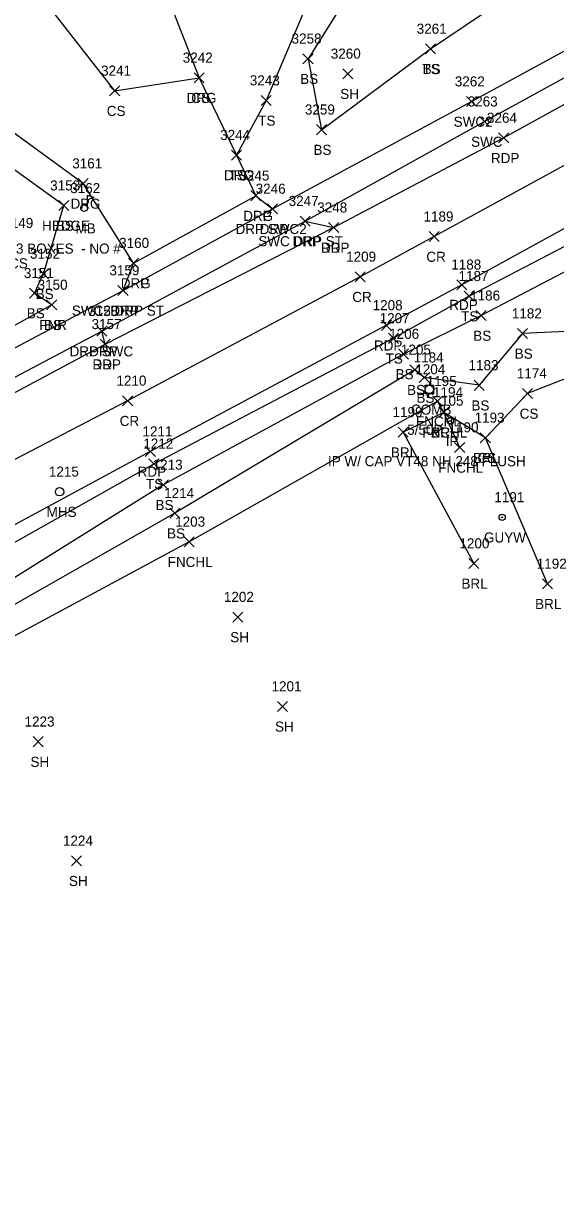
# Model space of a CAD drawing. Extents: x 1477930 to 1480780, y 774090 to 784647.
# Drawn here: x 1479576.9 to 1479682.6, y 774628 to 774857.9 of the extents above; entities that cross this region are included whole.
import ezdxf

# ---------------------------------------------------------------- set-up
doc = ezdxf.new("R2010")
doc.units = 0
for name, color, linetype in [('L_A', 7, 'Continuous'), ('L_C', 7, 'Continuous'), ('L_I', 7, 'Continuous'), ('L_TIC', 7, 'Continuous'), ('LABL', 7, 'Continuous'), ('LAHR', 7, 'Continuous'), ('LELB', 7, 'Continuous'), ('LFNC', 7, 'Continuous'), ('LMB', 7, 'Continuous'), ('M_A', 7, 'Continuous'), ('M_C', 7, 'Continuous'), ('M_I', 7, 'Continuous'), ('MPIR', 7, 'Continuous'), ('P_A', 7, 'Continuous'), ('P_I', 7, 'Continuous'), ('P_TIC', 7, 'Continuous'), ('PET', 7, 'Continuous'), ('PRC', 7, 'Continuous'), ('R_A', 7, 'Continuous'), ('R_I', 7, 'Continuous'), ('R_TIC', 7, 'Continuous'), ('RDG', 7, 'Continuous'), ('RDP', 7, 'Continuous'), ('RSW', 7, 'Continuous'), ('U_A', 7, 'Continuous'), ('U_C', 7, 'Continuous'), ('U_I', 7, 'Continuous'), ('UP', 7, 'Continuous'), ('UPGW', 7, 'Continuous'), ('USMH', 7, 'Continuous')]:
    doc.layers.add(name, color=color, linetype=linetype)

msp = doc.modelspace()

# ---------------------------------------------------------------- linework, layer by layer
at = {"layer": 'L_TIC'}
for points in [[(1479632.41, 774849.84), (1479634.41, 774851.84)], [(1479634.41, 774849.84), (1479632.41, 774851.84)], [(1479656.71, 774851.79), (1479658.71, 774853.79)], [(1479658.71, 774851.79), (1479656.71, 774853.79)], [(1479656.71, 774851.79), (1479658.71, 774853.79)], [(1479658.71, 774851.79), (1479656.71, 774853.79)], [(1479610.81, 774846.06), (1479612.81, 774848.06)], [(1479612.81, 774846.06), (1479610.81, 774848.06)], [(1479640.31, 774846.85), (1479642.31, 774848.85)], [(1479642.31, 774846.85), (1479640.31, 774848.85)], [(1479594.04, 774843.48), (1479596.04, 774845.48)], [(1479596.04, 774843.48), (1479594.04, 774845.48)], [(1479624.12, 774841.55), (1479626.12, 774843.55)], [(1479626.12, 774841.55), (1479624.12, 774843.55)], [(1479635.06, 774835.76), (1479637.06, 774837.76)], [(1479637.06, 774835.76), (1479635.06, 774837.76)], [(1479618.24, 774830.72), (1479620.24, 774832.72)], [(1479620.24, 774830.72), (1479618.24, 774832.72)], [(1479583.95, 774820.7), (1479585.95, 774822.7)], [(1479585.95, 774820.7), (1479583.95, 774822.7)], [(1479583.95, 774820.7), (1479585.95, 774822.7)], [(1479585.95, 774820.7), (1479583.95, 774822.7)], [(1479579.94, 774807.15), (1479581.94, 774809.15)], [(1479581.94, 774807.15), (1479579.94, 774809.15)], [(1479578.16, 774803.32), (1479580.16, 774805.32)], [(1479580.16, 774803.32), (1479578.16, 774805.32)], [(1479664.38, 774802.72), (1479666.38, 774804.72)], [(1479666.38, 774802.72), (1479664.38, 774804.72)], [(1479581.54, 774801), (1479583.54, 774803)], [(1479583.54, 774801), (1479581.54, 774803)], [(1479581.54, 774801), (1479583.54, 774803)], [(1479583.54, 774801), (1479581.54, 774803)], [(1479666.75, 774798.87), (1479668.75, 774800.87)], [(1479668.75, 774798.87), (1479666.75, 774800.87)], [(1479674.98, 774795.31), (1479676.98, 774797.31)], [(1479676.98, 774795.31), (1479674.98, 774797.31)], [(1479649.39, 774794.36), (1479651.39, 774796.36)], [(1479651.39, 774794.36), (1479649.39, 774796.36)], [(1479651.34, 774791.25), (1479653.34, 774793.25)], [(1479653.34, 774791.25), (1479651.34, 774793.25)], [(1479653.62, 774788.12), (1479655.62, 774790.12)], [(1479655.62, 774788.12), (1479653.62, 774790.12)], [(1479655.48, 774786.57), (1479657.48, 774788.57)], [(1479657.48, 774786.57), (1479655.48, 774788.57)], [(1479666.39, 774785.04), (1479668.39, 774787.04)], [(1479668.39, 774785.04), (1479666.39, 774787.04)], [(1479675.96, 774783.41), (1479677.96, 774785.41)], [(1479677.96, 774783.41), (1479675.96, 774785.41)], [(1479658.08, 774781.89), (1479660.08, 774783.89)], [(1479660.08, 774781.89), (1479658.08, 774783.89)], [(1479659.34, 774779.67), (1479661.34, 774781.67)], [(1479661.34, 774779.67), (1479659.34, 774781.67)], [(1479659.34, 774779.67), (1479661.34, 774781.67)], [(1479661.34, 774779.67), (1479659.34, 774781.67)], [(1479651.31, 774775.72), (1479653.31, 774777.72)], [(1479653.31, 774775.72), (1479651.31, 774777.72)], [(1479667.59, 774774.62), (1479669.59, 774776.62)], [(1479669.59, 774774.62), (1479667.59, 774776.62)], [(1479667.59, 774774.62), (1479669.59, 774776.62)], [(1479669.59, 774774.62), (1479667.59, 774776.62)], [(1479662.5, 774772.7), (1479664.5, 774774.7)], [(1479664.5, 774772.7), (1479662.5, 774774.7)], [(1479601.85, 774769.48), (1479603.85, 774771.48)], [(1479603.85, 774769.48), (1479601.85, 774771.48)], [(1479603.7, 774765.29), (1479605.7, 774767.29)], [(1479605.7, 774765.29), (1479603.7, 774767.29)], [(1479606, 774759.65), (1479608, 774761.65)], [(1479608, 774759.65), (1479606, 774761.65)], [(1479608.82, 774753.99), (1479610.82, 774755.99)], [(1479610.82, 774753.99), (1479608.82, 774755.99)], [(1479665.31, 774749.69), (1479667.31, 774751.69)], [(1479667.31, 774749.69), (1479665.31, 774751.69)], [(1479679.92, 774745.65), (1479681.92, 774747.65)], [(1479681.92, 774745.65), (1479679.92, 774747.65)], [(1479618.48, 774739.06), (1479620.48, 774741.06)], [(1479620.48, 774739.06), (1479618.48, 774741.06)], [(1479627.37, 774721.32), (1479629.37, 774723.32)], [(1479629.37, 774721.32), (1479627.37, 774723.32)], [(1479578.85, 774714.33), (1479580.85, 774716.33)], [(1479580.85, 774714.33), (1479578.85, 774716.33)], [(1479586.48, 774690.7), (1479588.48, 774692.7)], [(1479588.48, 774690.7), (1479586.48, 774692.7)]]:
    msp.add_lwpolyline(points, dxfattribs=at)
at = {"layer": 'LABL'}
msp.add_lwpolyline([(1479680.92, 774746.65), (1479668.59, 774775.62), (1479660.34, 774780.67), (1479652.31, 774776.72), (1479666.31, 774750.69)], dxfattribs=at)
at = {"layer": 'LAHR'}
msp.add_lwpolyline([(1479584.95, 774821.7), (1479570.44, 774832.18)], dxfattribs=at)
at = {"layer": 'LELB'}
for points in [[(1479657.71, 774852.79), (1479678.77, 774867.01), (1479701, 774889.08), (1479732.59, 774912.18), (1479741.3, 774922.23), (1479718.58, 774955.17), (1479686.39, 774981.9), (1479667.59, 775015.02), (1479668.33, 775036.3)], [(1479580.44, 774995.69), (1479587.48, 775002.68), (1479612.24, 774984.69), (1479628.11, 774970.45), (1479636.94, 774956.73), (1479624.94, 774926.71), (1479649.32, 774906.86), (1479653.38, 774932.32), (1479686.61, 774909.39), (1479687.43, 774900.61), (1479665.73, 774876.56), (1479654.12, 774867.16), (1479644.81, 774869.01), (1479633.41, 774850.84), (1479636.06, 774836.76), (1479657.71, 774852.79)], [(1479581.64, 774979.15), (1479580.44, 774995.69), (1479607.54, 774976.74), (1479621.25, 774963.52), (1479616.74, 774946.08), (1479607.55, 774933.66), (1479642.59, 774883.82), (1479625.12, 774842.55), (1479619.24, 774831.72)], [(1479515.09, 774886.51), (1479547.39, 774880.5), (1479577.54, 774866.92), (1479595.04, 774844.48), (1479611.81, 774847.06)], [(1479759.78, 774845.84), (1479743.76, 774848.1), (1479715.88, 774830.05), (1479665.38, 774803.72), (1479650.39, 774795.36), (1479602.85, 774770.48), (1479561.12, 774746.99), (1479522.68, 774719.79), (1479509.66, 774713.24), (1479482.17, 774702.33), (1479465.55, 774693.3), (1479450.04, 774680.68), (1479444.99, 774662.35), (1479439.28, 774645.05), (1479436.33, 774630.12), (1479434.69, 774607.73), (1479420.75, 774561.37), (1479408.24, 774515.83), (1479404.08, 774492.53), (1479401.08, 774483.2), (1479386.93, 774431.62)], [(1479759.78, 774845.84), (1479747.61, 774840.08), (1479717.72, 774826.7), (1479693.11, 774813.12), (1479667.75, 774799.87), (1479652.34, 774792.25), (1479604.7, 774766.29), (1479564.8, 774741.45), (1479523.94, 774717.4), (1479484.23, 774697.29), (1479467.35, 774689.75), (1479454.86, 774676.9), (1479444.99, 774662.35), (1479436.47, 774645.61)], [(1479755.47, 774826.43), (1479747.52, 774835), (1479732.81, 774826.8), (1479711.85, 774814.98), (1479703.35, 774801.53), (1479690.31, 774796.96), (1479675.98, 774796.31), (1479667.39, 774786.04), (1479656.48, 774787.57), (1479654.62, 774789.12), (1479607, 774760.65), (1479567.24, 774738.02), (1479525.29, 774711.93), (1479486.59, 774691.55), (1479469.23, 774685.68), (1479454.86, 774676.9)], [(1479767.9, 774827.58), (1479755.47, 774826.43), (1479737.02, 774821.5), (1479724.16, 774814.54), (1479699.51, 774793.2), (1479676.96, 774784.41), (1479668.59, 774775.62)], [(1479582.54, 774802), (1479579.16, 774804.32), (1479580.94, 774808.15), (1479584.95, 774821.7)]]:
    msp.add_lwpolyline(points, dxfattribs=at)
at = {"layer": 'LFNC'}
for points in [[(1479557.42, 774788.11), (1479582.54, 774802)], [(1479663.5, 774773.7), (1479660.34, 774780.67), (1479659.08, 774782.89), (1479609.82, 774754.99), (1479569.72, 774733.43), (1479526.46, 774709.45), (1479487.86, 774688.03), (1479452.66, 774667.9), (1479445.76, 774640.86), (1479438.34, 774612.12), (1479428.73, 774573.41), (1479420.36, 774539.52), (1479411.98, 774506.91), (1479408.88, 774492.5)]]:
    msp.add_lwpolyline(points, dxfattribs=at)
at = {"layer": 'LMB'}
for p, q in [((1479589.62, 774823.77), (1479590.92, 774823.39)), ((1479589.63, 774821.18), (1479589.63, 774823.77)), ((1479589.63, 774822.87), (1479590.91, 774823.38)), ((1479588.97, 774821.17), (1479588.97, 774821.17))]:
    msp.add_line(p, q, dxfattribs=at)
msp.add_circle((1479588.97, 774821.17), 0.656, dxfattribs=at)
at = {"layer": 'MPIR'}
for radius in [0.625, 0.0833]:
    msp.add_circle((1479661.67, 774778.99), radius, dxfattribs=at)
at = {"layer": 'P_TIC'}
for points in [[(1479671.22, 774834.12), (1479673.22, 774836.12)], [(1479673.22, 774834.12), (1479671.22, 774836.12)], [(1479637.49, 774816.33), (1479639.49, 774818.33)], [(1479639.49, 774816.33), (1479637.49, 774818.33)], [(1479657.45, 774814.54), (1479659.45, 774816.54)], [(1479659.45, 774814.54), (1479657.45, 774816.54)], [(1479642.75, 774806.57), (1479644.75, 774808.57)], [(1479644.75, 774806.57), (1479642.75, 774808.57)], [(1479662.95, 774805), (1479664.95, 774807)], [(1479664.95, 774805), (1479662.95, 774807)], [(1479648, 774796.94), (1479650, 774798.94)], [(1479650, 774796.94), (1479648, 774798.94)], [(1479592.15, 774793.19), (1479594.15, 774795.19)], [(1479594.15, 774793.19), (1479592.15, 774795.19)], [(1479596.62, 774781.97), (1479598.62, 774783.97)], [(1479598.62, 774781.97), (1479596.62, 774783.97)], [(1479601.12, 774771.9), (1479603.12, 774773.9)], [(1479603.12, 774771.9), (1479601.12, 774773.9)]]:
    msp.add_lwpolyline(points, dxfattribs=at)
at = {"layer": 'PET'}
for points in [[(1479458.85, 774725.87), (1479463.75, 774725.49), (1479503.78, 774746.04), (1479529.26, 774759.88), (1479547.26, 774769.69), (1479593.15, 774794.19), (1479638.49, 774817.33), (1479672.22, 774835.12), (1479713.57, 774857.96), (1479753.19, 774879.74), (1479794.61, 774902.46), (1479830.33, 774920.88), (1479861.74, 774937.83), (1479877.76, 774946.85), (1479905.13, 774960.92), (1479936.65, 774977.61), (1479958.81, 774989.4), (1479973, 774995.93), (1480008.35, 775014.95)], [(1479713.99, 774833.47), (1479663.95, 774806), (1479649, 774797.94), (1479602.12, 774772.9), (1479559.82, 774750.06), (1479518.06, 774728.17), (1479475.57, 774706.69), (1479465.7, 774701.25), (1479434.17, 774686.11), (1479428.66, 774666.26), (1479418.77, 774633.96), (1479413.82, 774614.69), (1479404.23, 774566.57), (1479393.7, 774517.71), (1479389.34, 774499.77)]]:
    msp.add_lwpolyline(points, dxfattribs=at)
at = {"layer": 'PRC'}
msp.add_lwpolyline([(1480015.89, 775005.87), (1479971.79, 774982.46), (1479929.14, 774959.03), (1479892.61, 774942.34), (1479860.44, 774925.31), (1479806.49, 774896.54), (1479658.45, 774815.54), (1479643.75, 774807.57), (1479597.62, 774782.97), (1479555.61, 774761.16), (1479513.42, 774740.32), (1479471, 774718.6), (1479432.73, 774701.1), (1479418.32, 774694.97), (1479344.83, 774660.92), (1479298.6, 774640.39), (1479262.12, 774624.4), (1479219.63, 774609.01), (1479186.74, 774593.83)], dxfattribs=at)
at = {"layer": 'R_TIC'}
for points in [[(1479610.81, 774846.06), (1479612.81, 774848.06)], [(1479612.81, 774846.06), (1479610.81, 774848.06)], [(1479664.84, 774841.34), (1479666.84, 774843.34)], [(1479666.84, 774841.34), (1479664.84, 774843.34)], [(1479667.4, 774837.36), (1479669.4, 774839.36)], [(1479669.4, 774837.36), (1479667.4, 774839.36)], [(1479618.24, 774830.72), (1479620.24, 774832.72)], [(1479620.24, 774830.72), (1479618.24, 774832.72)], [(1479587.8, 774825.08), (1479589.8, 774827.08)], [(1479589.8, 774825.08), (1479587.8, 774827.08)], [(1479622.05, 774822.66), (1479624.05, 774824.66)], [(1479624.05, 774822.66), (1479622.05, 774824.66)], [(1479622.05, 774822.66), (1479624.05, 774824.66)], [(1479624.05, 774822.66), (1479622.05, 774824.66)], [(1479625.34, 774820.05), (1479627.34, 774822.05)], [(1479627.34, 774820.05), (1479625.34, 774822.05)], [(1479625.34, 774820.05), (1479627.34, 774822.05)], [(1479627.34, 774820.05), (1479625.34, 774822.05)], [(1479631.83, 774817.63), (1479633.83, 774819.63)], [(1479633.83, 774817.63), (1479631.83, 774819.63)], [(1479631.83, 774817.63), (1479633.83, 774819.63)], [(1479633.83, 774817.63), (1479631.83, 774819.63)], [(1479637.49, 774816.33), (1479639.49, 774818.33)], [(1479639.49, 774816.33), (1479637.49, 774818.33)], [(1479597.76, 774809.29), (1479599.76, 774811.29)], [(1479599.76, 774809.29), (1479597.76, 774811.29)], [(1479597.76, 774809.29), (1479599.76, 774811.29)], [(1479599.76, 774809.29), (1479597.76, 774811.29)], [(1479595.7, 774803.86), (1479597.7, 774805.86)], [(1479597.7, 774803.86), (1479595.7, 774805.86)], [(1479595.7, 774803.86), (1479597.7, 774805.86)], [(1479597.7, 774803.86), (1479595.7, 774805.86)], [(1479591.5, 774795.78), (1479593.5, 774797.78)], [(1479593.5, 774795.78), (1479591.5, 774797.78)], [(1479591.5, 774795.78), (1479593.5, 774797.78)], [(1479593.5, 774795.78), (1479591.5, 774797.78)], [(1479592.15, 774793.19), (1479594.15, 774795.19)], [(1479594.15, 774793.19), (1479592.15, 774795.19)]]:
    msp.add_lwpolyline(points, dxfattribs=at)
at = {"layer": 'RDG'}
for points in [[(1479582.37, 774920.59), (1479606.56, 774913.22), (1479625.75, 774898.28), (1479624.88, 774886.81), (1479614.93, 774873.93), (1479610.96, 774876.63), (1479604.69, 774865.39), (1479611.81, 774847.06), (1479619.24, 774831.72), (1479623.05, 774823.66)], [(1479598.76, 774810.29), (1479588.8, 774826.08), (1479565.98, 774842.71), (1479549.85, 774844.2), (1479543.64, 774826.73), (1479535.87, 774827.58), (1479537.4, 774832.24), (1479514.07, 774836.92)]]:
    msp.add_lwpolyline(points, dxfattribs=at)
at = {"layer": 'RDP'}
for points in [[(1479596.7, 774804.86), (1479598.76, 774810.29), (1479623.05, 774823.66), (1479626.34, 774821.05)], [(1479632.83, 774818.63), (1479638.49, 774817.33)], [(1479593.15, 774794.19), (1479592.5, 774796.78)]]:
    msp.add_lwpolyline(points, dxfattribs=at)
at = {"layer": 'RSW'}
for points in [[(1479454.05, 774732.2), (1479457.36, 774735.51), (1479461.55, 774734.41), (1479499.97, 774753.7), (1479531.62, 774770.46), (1479545.78, 774777.94), (1479596.7, 774804.86), (1479626.34, 774821.05), (1479665.84, 774842.34), (1479709.72, 774866.29), (1479748.23, 774887.23), (1479790.98, 774910.55), (1479825.88, 774929.42), (1479857.89, 774946.35), (1479880.81, 774958.36), (1479898.02, 774967.81), (1479932.31, 774985.56), (1479966.42, 775003.67), (1480005.03, 775023.74)], [(1479458.85, 774725.87), (1479459.6, 774730), (1479502.04, 774749.23), (1479530.65, 774764.31), (1479546.64, 774772.58), (1479592.5, 774796.78), (1479632.83, 774818.63), (1479668.4, 774838.36), (1479711.89, 774862.21), (1479750.54, 774883.44), (1479792.95, 774906.12), (1479828.15, 774924.96), (1479859.81, 774941.82), (1479882.29, 774953.43), (1479899.45, 774962.93), (1479935.39, 774981.77), (1479958.84, 774993.68), (1479967.68, 774998.52), (1480006.53, 775018.83)]]:
    msp.add_lwpolyline(points, dxfattribs=at)
at = {"layer": 'UP'}
for p, q in [((1479656.63, 774784.38), (1479656.63, 774786.05)), ((1479656.63, 774786.05), (1479658.29, 774786.05)), ((1479657.71, 774786.88), (1479657.46, 774786.05)), ((1479657.46, 774785.22), (1479657.46, 774785.22)), ((1479658.29, 774786.05), (1479658.29, 774784.38)), ((1479658.29, 774784.38), (1479656.63, 774784.38)), ((1479657.21, 774783.55), (1479657.46, 774784.38))]:
    msp.add_line(p, q, dxfattribs=at)
msp.add_circle((1479657.46, 774785.22), 0.833, dxfattribs=at)
at = {"layer": 'UPGW'}
for radius in [0.625, 0.0833]:
    msp.add_circle((1479671.93, 774759.85), radius, dxfattribs=at)
at = {"layer": 'USMH'}
for p, q in [((1479584.12, 774764.92), (1479584.12, 774764.92)), ((1479584.95, 774764.92), (1479584.95, 774764.92))]:
    msp.add_line(p, q, dxfattribs=at)
msp.add_circle((1479584.12, 774764.92), 0.833, dxfattribs=at)

# ---------------------------------------------------------------- texts
at = {"layer": 'L_A'}
for s, p in [('TS', (1479656.12, 774847.79)), ('BS', (1479656.15, 774847.79)), ('BS', (1479631.85, 774845.84)), ('SH', (1479639.8, 774842.85)), ('CS', (1479610.25, 774842.06)), ('CS', (1479593.48, 774839.48)), ('TS', (1479623.53, 774837.55)), ('BS', (1479634.5, 774831.76)), ('TS', (1479617.65, 774826.72)), ('HEDGE', (1479580.65, 774816.7)), ('BS', (1479583.39, 774816.7)), ('MB', (1479587.28, 774816.17)), ('CS', (1479574.1, 774809.25)), ('BS', (1479579.38, 774803.15)), ('BS', (1479577.6, 774799.32)), ('FNR', (1479580.08, 774797)), ('BS', (1479580.99, 774797)), ('TS', (1479663.79, 774798.72)), ('BS', (1479666.19, 774794.87)), ('TS', (1479648.8, 774790.36)), ('BS', (1479674.42, 774791.31)), ('BS', (1479650.78, 774787.25)), ('BS', (1479653.06, 774784.12)), ('BS', (1479654.92, 774782.57)), ('BS', (1479665.83, 774781.04)), ('CS', (1479675.4, 774779.41)), ('FNCHL', (1479654.83, 774777.89)), ('FNCHL', (1479656.09, 774775.67)), ('BRL', (1479657.88, 774775.67)), ('BRL', (1479649.85, 774771.72)), ('BRL', (1479666.13, 774770.62)), ('CS', (1479667.03, 774770.62)), ('FNCHL', (1479659.25, 774768.7)), ('TS', (1479601.26, 774765.48)), ('BS', (1479603.15, 774761.29)), ('BS', (1479605.44, 774755.65)), ('FNCHL', (1479605.57, 774749.99)), ('BRL', (1479663.85, 774745.69)), ('BRL', (1479678.46, 774741.65)), ('SH', (1479617.97, 774735.06)), ('SH', (1479626.86, 774717.32)), ('SH', (1479578.34, 774710.33)), ('SH', (1479585.97, 774686.7))]:
    msp.add_text(s, height=2, dxfattribs=at).set_placement(p)
at = {"layer": 'L_C'}
msp.add_text('3 BOXES  - NO #', height=2, dxfattribs=at).set_placement((1479575.46, 774812.17))
at = {"layer": 'L_I'}
for s, p in [('3261', (1479654.97, 774855.79)), ('3261', (1479654.97, 774855.79)), ('3258', (1479630.15, 774853.84)), ('3242', (1479608.55, 774850.06)), ('3260', (1479637.92, 774850.85)), ('3241', (1479592.35, 774847.48)), ('3243', (1479621.86, 774845.55)), ('3259', (1479632.79, 774839.76)), ('3244', (1479615.98, 774834.72)), ('3153', (1479582.25, 774824.7)), ('3153', (1479582.25, 774824.7)), ('3162', (1479586.23, 774824.17)), ('3149', (1479572.95, 774817.25)), ('3152', (1479578.25, 774811.15)), ('3151', (1479577.03, 774807.32)), ('1187', (1479663.26, 774806.72)), ('3150', (1479579.76, 774805)), ('3150', (1479579.76, 774805)), ('1186', (1479665.57, 774802.87)), ('1182', (1479673.85, 774799.31)), ('1207', (1479647.62, 774798.36)), ('1206', (1479649.51, 774795.25)), ('1205', (1479651.84, 774792.12)), ('1184', (1479654.36, 774790.57)), ('1183', (1479665.26, 774789.04)), ('1195', (1479656.95, 774785.89)), ('1174', (1479674.83, 774787.41)), ('1194', (1479658.21, 774783.67)), ('1194', (1479658.21, 774783.67)), ('1199', (1479650.17, 774779.72)), ('1193', (1479666.46, 774778.62)), ('1193', (1479666.46, 774778.62)), ('1190', (1479661.29, 774776.7)), ('1212', (1479600.72, 774773.48)), ('1213', (1479602.58, 774769.29)), ('1214', (1479604.87, 774763.65)), ('1203', (1479607.05, 774757.99)), ('1200', (1479663.45, 774753.69)), ('1192', (1479678.79, 774749.65)), ('1202', (1479616.71, 774743.06)), ('1201', (1479626.17, 774725.32)), ('1223', (1479577.16, 774718.33)), ('1224', (1479584.78, 774694.7))]:
    msp.add_text(s, height=2, dxfattribs=at).set_placement(p)
at = {"layer": 'M_A'}
msp.add_text('IP', height=2, dxfattribs=at).set_placement((1479660.72, 774773.99))
at = {"layer": 'M_C'}
msp.add_text('IP W/ CAP VT48 NH 248 FLUSH', height=2, dxfattribs=at).set_placement((1479637.37, 774769.99))
at = {"layer": 'M_I'}
msp.add_text('105', height=2, dxfattribs=at).set_placement((1479659.79, 774781.99))
at = {"layer": 'P_A'}
for s, p in [('RDP', (1479669.7, 774830.12)), ('RDP', (1479635.98, 774812.33)), ('CR', (1479656.89, 774810.54)), ('CR', (1479642.19, 774802.57)), ('RDP', (1479661.44, 774801)), ('RDP', (1479646.49, 774792.94)), ('RDP', (1479590.64, 774789.19)), ('CR', (1479596.05, 774777.97)), ('RDP', (1479599.61, 774767.9))]:
    msp.add_text(s, height=2, dxfattribs=at).set_placement(p)
at = {"layer": 'P_I'}
for s, p in [('3264', (1479668.91, 774838.12)), ('3248', (1479635.23, 774820.33)), ('1189', (1479656.32, 774818.54)), ('1209', (1479640.97, 774810.57)), ('1188', (1479661.83, 774809)), ('1208', (1479646.23, 774800.94)), ('3157', (1479590.46, 774797.19)), ('1210', (1479595.4, 774785.97)), ('1211', (1479600.56, 774775.9))]:
    msp.add_text(s, height=2, dxfattribs=at).set_placement(p)
at = {"layer": 'R_A'}
for s, p in [('DRG', (1479609.3, 774842.06)), ('SWC2', (1479662.31, 774837.34)), ('SWC', (1479665.76, 774833.36)), ('DRG', (1479616.73, 774826.72)), ('DRG', (1479586.29, 774821.08)), ('DRG', (1479620.54, 774818.66)), ('DRP', (1479620.54, 774818.66)), ('DRP SWC2', (1479619.03, 774816.05)), ('DRP', (1479623.82, 774816.05)), ('SWC DRP ST', (1479623.55, 774813.63)), ('DRP', (1479630.32, 774813.63)), ('DRP', (1479635.98, 774812.33)), ('DRG', (1479596.25, 774805.29)), ('DRP', (1479596.25, 774805.29)), ('SWC2 DRP ST', (1479586.56, 774799.86)), ('DRP', (1479594.18, 774799.86)), ('DRP SWC', (1479586.09, 774791.78)), ('DRP', (1479589.99, 774791.78)), ('DRP', (1479590.64, 774789.19))]:
    msp.add_text(s, height=2, dxfattribs=at).set_placement(p)
at = {"layer": 'R_I'}
for s, p in [('3242', (1479608.55, 774850.06)), ('3262', (1479662.53, 774845.34)), ('3263', (1479665.09, 774841.36)), ('3244', (1479615.98, 774834.72)), ('3161', (1479586.63, 774829.08)), ('3245', (1479619.79, 774826.66)), ('3245', (1479619.79, 774826.66)), ('3246', (1479623.02, 774824.05)), ('3246', (1479623.02, 774824.05)), ('3247', (1479629.57, 774821.63)), ('3247', (1479629.57, 774821.63)), ('3248', (1479635.23, 774820.33)), ('3160', (1479595.93, 774813.29)), ('3160', (1479595.93, 774813.29)), ('3159', (1479594, 774807.86)), ('3159', (1479594, 774807.86)), ('3158', (1479589.81, 774799.78)), ('3158', (1479589.81, 774799.78)), ('3157', (1479590.46, 774797.19))]:
    msp.add_text(s, height=2, dxfattribs=at).set_placement(p)
at = {"layer": 'U_A'}
for s, p in [('COMB', (1479653.85, 774780.22)), ('MHS', (1479581.54, 774759.92)), ('GUYW', (1479668.32, 774754.85))]:
    msp.add_text(s, height=2, dxfattribs=at).set_placement(p)
at = {"layer": 'U_C'}
msp.add_text('5/50P', height=2, dxfattribs=at).set_placement((1479653.09, 774776.22))
at = {"layer": 'U_I'}
for s, p in [('1204', (1479654.69, 774788.22)), ('1215', (1479581.99, 774767.92)), ('1191', (1479670.37, 774762.85))]:
    msp.add_text(s, height=2, dxfattribs=at).set_placement(p)

doc.saveas('drawing.dxf')
